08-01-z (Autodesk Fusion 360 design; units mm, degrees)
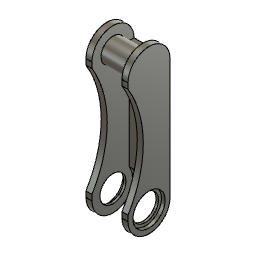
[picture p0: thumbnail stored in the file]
sketch "スケッチ1" plane through (0, 0, 0) normal (1, 0, 0) x axis (0, 0, -1)
  circle C1 centre (0, 40) radius 4
  point P1 (0, 0)
  point P2 (0, 40)
  vertical P1 P2
  dimension "d1" distance P1 P2 = 40
  dimension "d2" diameter C1 = 8
extrude "押し出し1" new body sketch "スケッチ1" distance 10
sketch "スケッチ2" plane through (5, 0, 0) normal (1, 0, 0) x axis (0, 0, -1)
  line L1 (7, 40) -> (7, 0)
  line L2 (-7, 0) -> (-7, 40)
  line L3 (0, 40) -> (0, 0)
  circle C1 centre (0, 40) radius 4
  arc A1 centre (0, 40) radius 7 clockwise from (-7, 40) to (7, 40)
  arc A2 centre (0, 0) radius 7 clockwise from (7, 0) to (-7, 0)
  point P1 (0, 0)
  point P7 (0, 0)
  point P8 (0, 40)
  tangent L1 A1
  tangent A1 L2
  parallel L1 L2
  tangent L2 A2
  tangent L1 A2
  vertical L3
  coincident P1 P7
  dimension "d5" distance P7 P8 = 40
  dimension "d6" radius A1 = 7
extrude "押し出し2" add sketch "スケッチ2" profile of C1 L1 A1 L2 A2 along normal blind 2
mirror "ミラー" mirrorStitchTolerance 0.1
sketch "スケッチ3" plane through (0, 0, 0) normal (1, 0, 0) x axis (0, 0, -1)
  line L1 (7, 40) -> (5.4, 40)
  line L2 (7, 0) -> (7, 40)
  line L3 (5.4, 0) -> (7, 0)
  line L4 (5.4, 40) -> (5.4, 0)
  point P3 (7, 40)
  point P6 (7, 40)
  point P4 (7, 0)
  point P7 (7, 0)
  horizontal L1
  vertical L2
  horizontal L3
  vertical L4
  coincident P3 P6
  coincident P4 P7
  dimension "d11" distance L2 L4 = 1.6
extrude "押し出し3" add sketch "スケッチ3" distance 10
sketch "スケッチ4" plane through (0, 0, 0) normal (1, 0, 0) x axis (0, 0, -1)
  circle C1 centre (-36.9324, 20) radius 35
  arc A1 centre (0, 0) radius 7 clockwise from (7, 0) to (-7, 0)
  arc A2 centre (0, 40) radius 7 clockwise from (-7, 40) to (7, 40)
  tangent C1 A1
  tangent C1 A2
  dimension "d14" diameter C1 = 70
extrude "押し出し4" cut sketch "スケッチ4" profile of C1 no distance stored
sketch "スケッチ5" plane through (0, 0, 0) normal (1, 0, 0) x axis (0, 0, -1)
  circle C1 centre (0, 0) radius 6.5
  point P1 (0, 0)
  point P2 (0, 0)
  coincident P1 P2
  dimension "d16" diameter C1 = 13
extrude "押し出し5" cut sketch "スケッチ5" distance 10
hole "穴1" HoleDepth 2 HoleDiameter 8.7 TipAngle 118 CBDepth 1.2 CBDiameter 10.7
hole "穴2" HoleDepth 2 HoleDiameter 8.7 TipAngle 118 CBDepth 1.2 CBDiameter 10.7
